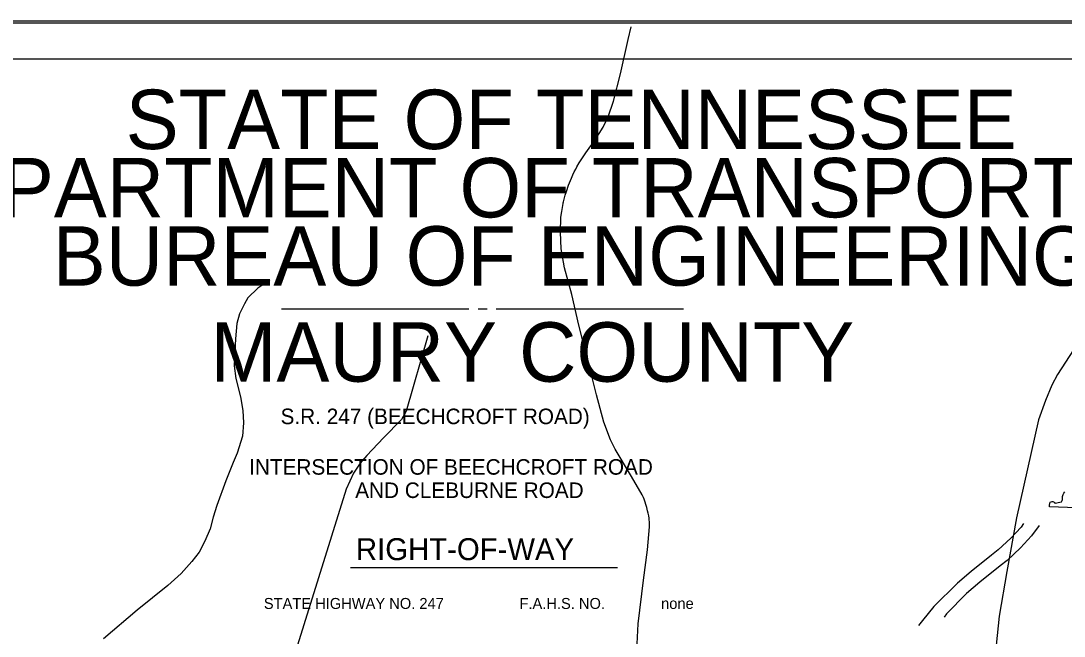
# Model space of a CAD drawing. Extents: x 1577619 to 1828281, y 483481 to 598136.
# Drawn here: x 1672781 to 1695627, y 526740 to 540205 of the extents above; entities that cross this region are included whole.
import ezdxf

# ---------------------------------------------------------------- set-up
doc = ezdxf.new("R2010")
doc.units = 0
for name, color, linetype in [('DESIGN - CONTOURS - Intermediate with optional Text', 7, 'Continuous'), ('DESIGN - SHEET - Corner Text', 7, 'Continuous'), ('DESIGN - SHEET - Linework', 7, 'Continuous'), ('DESIGN - SHEET - Plot Shape', 7, 'Continuous'), ('SURVEY - CENTERLINE - Preliminary', 7, 'Continuous'), ('SURVEY - CENTERLINE - Preliminary Text', 7, 'Continuous'), ('SURVEY - VEGETATION - Features with Text', 7, 'Continuous')]:
    doc.layers.add(name, color=color, linetype=linetype)

msp = doc.modelspace()

# ---------------------------------------------------------------- linework, layer by layer
at = {"layer": 'DESIGN - CONTOURS - Intermediate with optional Text'}
msp.add_lwpolyline([(1678233, 534530), (1677969, 534355), (1677751, 534142), (1677675, 534010), (1677569, 533792), (1677513, 533584), (1677478, 533249), (1677465, 532958), (1677454, 532657), (1677487, 532379), (1677590, 531979), (1677643, 531677), (1677656, 531408), (1677632, 531117), (1677519, 530747), (1677433, 530537), (1677269, 530135), (1677073, 529599), (1676993, 529341), (1676926, 529091), (1676812, 528816), (1676683, 528580), (1676526, 528371), (1676291, 528111), (1676000, 527845), (1675326, 527307), (1674588, 526682)], dxfattribs=at)
msp.add_lwpolyline([(1678233, 534530), (1677969, 534355), (1677751, 534142), (1677675, 534010), (1677569, 533792), (1677513, 533584), (1677478, 533249), (1677465, 532958), (1677454, 532657), (1677487, 532379), (1677590, 531979), (1677643, 531677), (1677656, 531408), (1677632, 531117), (1677519, 530747), (1677433, 530537), (1677269, 530135), (1677073, 529599), (1676993, 529341), (1676926, 529091), (1676812, 528816), (1676683, 528580), (1676526, 528371), (1676291, 528111), (1676000, 527845), (1675326, 527307), (1674588, 526682)], dxfattribs=at)
at = {"layer": 'DESIGN - SHEET - Linework'}
for p, q in [((1647461, 540205), (1715541, 540205)), ((1678492, 533906), (1682592, 533906)), ((1682792, 533906), (1682992, 533906)), ((1683192, 533906), (1687292, 533906)), ((1680000, 528241), (1685845, 528241))]:
    msp.add_line(p, q, dxfattribs=at)
for points in [[(1652139, 539377), (1715107, 539377), (1715107, 497377), (1652139, 497377), (1652139, 539377)], [(1695312, 529634), (1695312, 529646), (1695324, 529670), (1695344, 529682), (1695366, 529686), (1695380, 529686), (1695394, 529682), (1695406, 529672), (1695416, 529660), (1695428, 529654), (1695440, 529652), (1695468, 529658), (1695496, 529664), (1695532, 529672), (1695566, 529682), (1695578, 529690), (1695586, 529710), (1695592, 529732), (1695592, 529766), (1695592, 529798), (1695600, 529820), (1695608, 529842), (1695620, 529870), (1695640, 529896)], [(1696092, 529540), (1695306, 529570), (1695308, 529596), (1695310, 529622), (1695312, 529634)]]:
    msp.add_lwpolyline(points, dxfattribs=at)
at = {"layer": 'DESIGN - SHEET - Plot Shape'}
for points in [[(1647501, 540165), (1715501, 540165), (1715501, 496589), (1647501, 496589)], [(1648737, 539377), (1715107, 539377), (1715107, 497377), (1648737, 497377)]]:
    msp.add_lwpolyline(points, close=True, dxfattribs=at)
at = {"layer": 'SURVEY - CENTERLINE - Preliminary'}
msp.add_lwpolyline([(1699664, 538981), (1699319, 538410), (1698972, 537842), (1695481, 532469), (1695357, 532234), (1695217, 531899), (1695067, 531470), (1694585, 529330), (1694371, 528156), (1694207, 527174), (1693664, 521961), (1693575, 521307), (1693483, 520786), (1693198, 519751), (1691959, 516195)], dxfattribs=at)
msp.add_lwpolyline([(1699664, 538981), (1699319, 538410), (1698972, 537842), (1695481, 532469), (1695357, 532234), (1695217, 531899), (1695067, 531470), (1694585, 529330), (1694371, 528156), (1694207, 527174), (1693664, 521961), (1693575, 521307), (1693483, 520786), (1693198, 519751), (1691959, 516195)], dxfattribs=at)
at = {"layer": 'SURVEY - CENTERLINE - Preliminary Text'}
for points in [[(1686256, 526135), (1686301, 527012), (1686414, 527964), (1686503, 528626), (1686547, 529130), (1686546, 529244), (1686542, 529287), (1686537, 529321), (1686530, 529370), (1686518, 529431), (1686507, 529482), (1686486, 529558), (1686428, 529738), (1686414, 529771), (1686408, 529787), (1686403, 529802), (1686389, 529831), (1686155, 530231), (1685799, 530831), (1685696, 531035), (1685547, 531422), (1685387, 532021), (1685238, 532604), (1685002, 533545), (1684845, 534216), (1684689, 534797), (1684616, 535217), (1684595, 535582), (1684609, 535910), (1684626, 536035), (1684632, 536075), (1684656, 536205), (1684660, 536223), (1684665, 536246), (1684702, 536390), (1684727, 536473), (1684773, 536607), (1684836, 536765), (1684867, 536833), (1684900, 536901), (1684931, 536961), (1684957, 537009), (1685008, 537096), (1685152, 537315), (1685354, 537604), (1685530, 537881), (1685645, 538101), (1685761, 538444), (1685915, 539045), (1686082, 539798), (1686146, 540075)], [(1681695, 533313), (1681215, 531662), (1681113, 531484), (1680722, 531076), (1680359, 530690), (1680211, 530522), (1680066, 530307), (1679906, 529953), (1676801, 520023), (1676699, 519793), (1676512, 519506), (1675717, 518547)], [(1681695, 533313), (1681215, 531662), (1681113, 531484), (1680722, 531076), (1680359, 530690), (1680211, 530522), (1680066, 530307), (1679906, 529953), (1676801, 520023), (1676699, 519793), (1676512, 519506), (1675717, 518547)]]:
    msp.add_lwpolyline(points, dxfattribs=at)
at = {"layer": 'SURVEY - VEGETATION - Features with Text'}
for points in [[(1694740, 529203), (1694683, 529128), (1694460, 528881), (1694182, 528625), (1694037, 528511), (1693588, 528151), (1693292, 527899), (1692777, 527386), (1692523, 527083), (1692435, 526969)], [(1694740, 529203), (1694683, 529128), (1694460, 528881), (1694182, 528625), (1694037, 528511), (1693588, 528151), (1693292, 527899), (1692777, 527386), (1692523, 527083), (1692435, 526969)], [(1695083, 529160), (1694914, 528937), (1694673, 528670), (1694377, 528397), (1694224, 528276), (1693779, 527919), (1693490, 527676), (1693051, 527228), (1692997, 527157)]]:
    msp.add_lwpolyline(points, dxfattribs=at)

# ---------------------------------------------------------------- texts
at = {"layer": 'DESIGN - SHEET - Corner Text'}
for s, height, p in [('STATE OF TENNESSEE', 1300, (1675077, 537399)), ('DEPARTMENT OF TRANSPORTATION', 1300, (1669928, 535904)), ('BUREAU OF ENGINEERING', 1300, (1673480, 534410)), ('MAURY COUNTY', 1300, (1676930, 532308)), ('S.R. 247 (BEECHCROFT ROAD) ', 340, (1678468, 531379)), ('INTERSECTION OF BEECHCROFT ROAD', 340, (1677780, 530273)), ('AND CLEBURNE ROAD', 340, (1680103, 529763)), ('RIGHT-OF-WAY', 480, (1680119, 528403)), ('STATE HIGHWAY NO. 247', 240, (1678102, 527335)), ('F.A.H.S. NO.    ', 240, (1683700, 527335)), ('none', 240, (1686801, 527335))]:
    msp.add_text(s, height=height, dxfattribs=at).set_placement(p)

doc.saveas('drawing.dxf')
